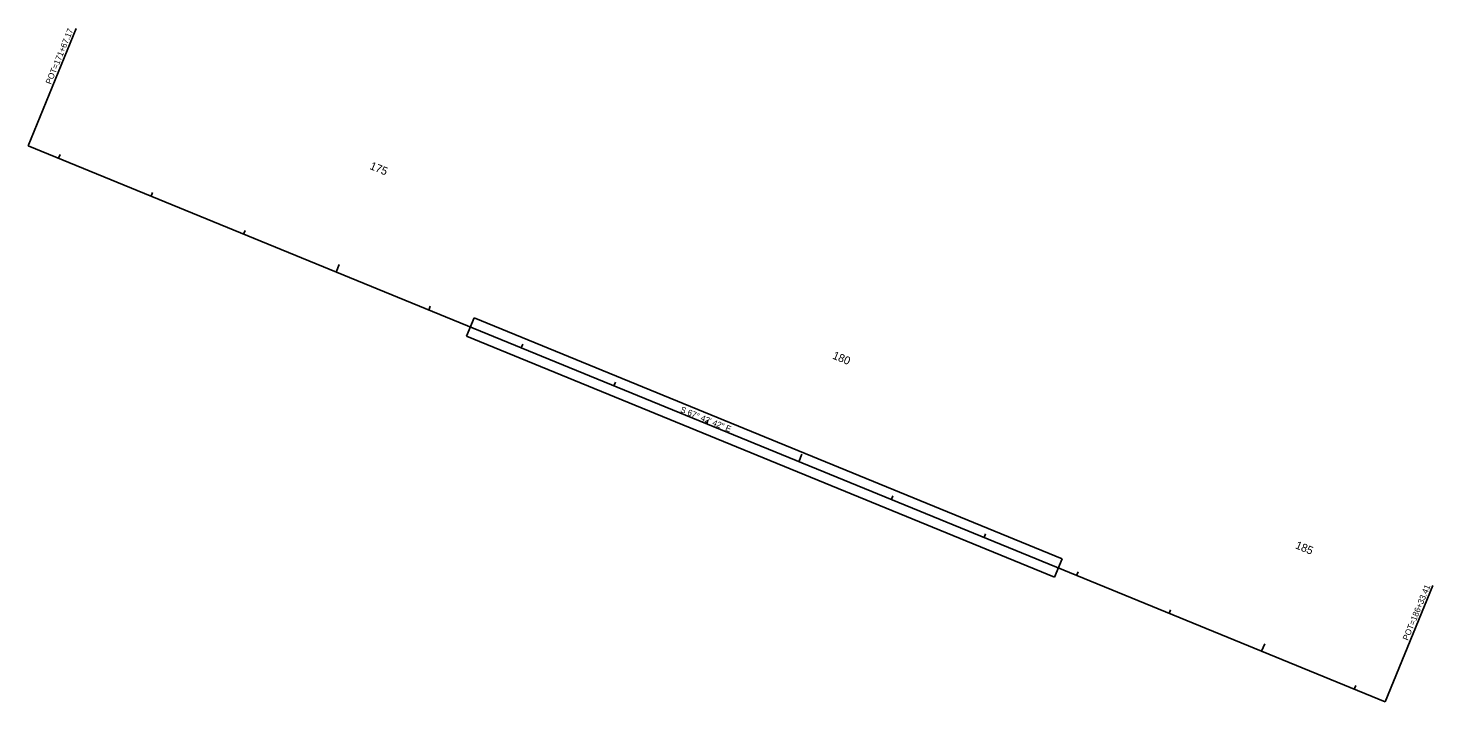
# Model space of a CAD drawing. Extents: x 1892617 to 1906752, y 1106408 to 1134459.
# Drawn here: x 1904865 to 1906270, y 1109803 to 1110477 of the extents above; entities that cross this region are included whole.
import ezdxf

# ---------------------------------------------------------------- set-up
doc = ezdxf.new("R2010")
doc.units = 0
for name, color, linetype in [('RD_HC_Cl', 7, 'Continuous'), ('RD_HC_Data', 7, 'Continuous'), ('RD_HC_Data_Tic', 7, 'Continuous'), ('RD_HC_TX_Sta50', 7, 'Continuous'), ('RD_PD_Final_TrvlWay', 7, 'Continuous')]:
    doc.layers.add(name, color=color, linetype=linetype)

msp = doc.modelspace()

# ---------------------------------------------------------------- linework, layer by layer
at = {"layer": 'RD_HC_Cl'}
msp.add_line((1904865.2, 1110359.1), (1906221.9, 1109803), dxfattribs=at)
at = {"layer": 'RD_HC_Data'}
for p, q in [((1904865.2, 1110359.1), (1904913.3, 1110476.4)), ((1906221.9, 1109803), (1906269.6, 1109919.5))]:
    msp.add_line(p, q, dxfattribs=at)
at = {"layer": 'RD_HC_Data_Tic'}
for p, q in [((1904895.6, 1110346.7), (1904897.1, 1110350.4)), ((1904988.1, 1110308.7), (1904989.6, 1110312.4)), ((1905080.6, 1110270.8), (1905082.1, 1110274.5)), ((1905173.2, 1110232.9), (1905176.2, 1110240.3)), ((1905265.7, 1110194.9), (1905267.2, 1110198.6)), ((1905358.2, 1110157), (1905359.7, 1110160.7)), ((1905450.7, 1110119.1), (1905452.3, 1110122.8)), ((1905543.3, 1110081.2), (1905544.8, 1110084.9)), ((1905635.8, 1110043.2), (1905638.8, 1110050.6)), ((1905728.3, 1110005.3), (1905729.8, 1110009)), ((1905820.9, 1109967.4), (1905822.4, 1109971.1)), ((1905913.4, 1109929.5), (1905914.9, 1109933.2)), ((1906005.9, 1109891.5), (1906007.4, 1109895.2)), ((1906098.4, 1109853.6), (1906101.5, 1109861)), ((1906191, 1109815.7), (1906192.5, 1109819.4))]:
    msp.add_line(p, q, dxfattribs=at)
at = {"layer": 'RD_PD_Final_TrvlWay'}
for p, q in [((1905303.5, 1110168.6), (1905311.1, 1110187.1)), ((1905311.1, 1110187.1), (1905898.9, 1109946.2)), ((1905303.5, 1110168.6), (1905891.3, 1109927.7)), ((1905898.9, 1109946.2), (1905891.3, 1109927.7))]:
    msp.add_line(p, q, dxfattribs=at)

# ---------------------------------------------------------------- texts
at = {"layer": 'RD_HC_Data'}
for s, rotation, p in [('POT=171+67.17', 67.7118, (1904888, 1110420)), ('S 67%%d 42\' 42" E', 337.7118, (1905516.7, 1110093.1)), ('POT=186+33.41', 67.7118, (1906244.7, 1109863.9))]:
    msp.add_text(s, height=6, rotation=rotation, dxfattribs=at).set_placement(p)
at = {"layer": 'RD_HC_TX_Sta50'}
for s, p in [('175', (1905206.1, 1110336.1)), ('180', (1905668.7, 1110146.5)), ('185', (1906131.4, 1109956.8))]:
    msp.add_text(s, height=8, rotation=337.7118, dxfattribs=at).set_placement(p)

doc.saveas('drawing.dxf')
